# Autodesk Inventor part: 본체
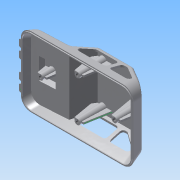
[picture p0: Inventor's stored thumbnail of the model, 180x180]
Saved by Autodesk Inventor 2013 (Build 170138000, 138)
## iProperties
Created: 2015-05
Part Number: 본체
Material: ABS 플라스틱
Document SubType Name: Modeling
Designer: Administrator
Density: 7.85 g/cm^3
Mass: 239.611 g
Surface Area: 315.025 cm^2
Volume: 30.5238 cm^3
Author: Administrator
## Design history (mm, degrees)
sketch "스케치1"
  geometry: L1 (0, 0)-(122, 0); L2 (92, 30)-(53.826, 30); L3 (53.826, 30)-(42, 11.075); L4 (42, 11.075)-(2.412, 9); L5 (2.412, 9)-(0, 0); L6 (122, 0)-(122, 10); L7 (92, 30)-(122, 10); L8 (122, 0)-(118.738, 12.175)
  constraints: 16 end point, 1 horizontal, 1 parallel, 1 perpendicular, 1 point on line
  dimensions: "d0" = 122 distance of L1.start L1.end; "d1" = 105 deg angle of L1 L5; "d2" = 30 distance between parallel lines of L2 L1; "d3" = 30 horizontal distance of L1.end L2.start; "d4" = 9 vertical distance of L1.start L4.end; "d6" = 3 deg angle of L1 L4; "d9" = 125 deg angle of L3 L4; "d10" = 42 horizontal distance of L1.start L3.end; "d33" = 20 vertical distance of L6.end L2.start; "d34" = 105 deg angle of L1 L8
node "작업 평면1"
extrude "돌출4" new body sketch "스케치1" stored distance "d35" = 76; taper "d36" = 0 deg
node "작업 평면4"
sketch "스케치7"
  geometry: L1 (12.175, 38)-(30, 38) reference; L2 (0, 38)-(12.175, 38) reference; L3 (0, -38)-(0, 38) reference; L4 (30, -38)-(30, 38) reference; L5 (30, -38)-(12.175, -38) reference; L6 (12.175, -38)-(0, -38) reference; L7 (0, -38)-(30, -29.962); L8 (0, 38)-(30, 29.962); 1 further point
  constraints: 4 end point, 2 point on line
  dimensions: "d40" = 105 deg angle of L3 L7; "d41" = 105 deg angle of L3 L8
extrude "돌출5" cut sketch "스케치7" stored distance "d42" = 76; taper "d43" = 0 deg
sketch "스케치9"
  geometry: L1 (8.121, 48.588)-(28.121, 48.588); L2 (28.121, 48.588)-(28.121, 22.588); L3 (28.121, 22.588)-(8.121, 22.588); L4 (8.121, 22.588)-(8.121, 48.588); L5 (8.121, 48.588)-(28.121, 22.588); L6 (28.121, 48.588)-(8.121, 22.588); L7 (-2.879, -2.412)-(-2.879, 73.588) reference; 4 further points
  constraints: 12 end point, 4 midpoint, 2 parallel, 1 horizontal, 1 horizontal alignment, 1 perpendicular
  dimensions: "d53" = 11 distance between parallel lines of L4 L7; "d54" = 20 distance between parallel lines of L2 L4; "d55" = 26 distance between parallel lines of L3 L1
extrude "돌출7" join sketch "스케치9" distance "d56" = 5; taper "d57" = -20 deg
fillet "모깎기1" dims "d69" = 12
feature "쉘2" dims "d44" = 2
node "작업 평면5"
sketch "스케치8"
  geometry: L1 (42, 11.075)-(53.826, 30) reference; L2 (53.826, 30)-(92, 30) reference; L3 (112.986, 10)-(90.486, 25); L4 (90.486, 25)-(56.597, 25); L5 (56.597, 25)-(47.224, 10); L6 (47.224, 10)-(112.986, 10); L7 (81.224, 25)-(81.224, 10); L8 (84.986, 25)-(84.986, 10); 3 further points; 1 other entity
  constraints: 12 end point, 4 point on line, 2 perpendicular, 1 parallel, 2 other
  dimensions: "d46" = 5 distance between parallel lines of L4 L2; "d47" = 15 distance between parallel lines of L6 L4; "d48" = 5 dimension on L3; "d49" = 34 distance of L7.end L5.end; "d50" = 28 distance of L3.start L8.end
extrude "돌출6" cut sketch "스케치8" stored distance "d51" = 76; taper "d52" = 0 deg
node "작업 평면6"
sketch "스케치14"
  geometry: L1 (98.679, -73.929)-(0.139, -73.929) reference; L2 (-9.521, -64.27)-(-9.521, -11.73) reference; L3 (0.139, -2.071)-(98.679, -2.071) reference; L4 (108.338, -11.73)-(108.338, -64.27) reference; L5 (98.679, -1.071)-(0.139, -1.071); L6 (-10.521, -11.73)-(-10.521, -64.27); L7 (0.139, -74.929)-(98.679, -74.929); L8 (109.338, -64.27)-(109.338, -11.73); 5 further points; 4 other entities
  constraints: 8 end point, 7 parallel, 16 other
  dimensions: "d87" = 1 distance between parallel lines of L3 L5
extrude "돌출10" join sketch "스케치14" distance "d88" = 1; taper "d89" = 0 deg
node "작업 평면9"
sketch "스케치15" dims "d103" = 4
  geometry: L1 (0, 25)-(0, -25); C1 r 4 at (0, -10); C2 r 4 at (0, 10); 6 further points
  constraints: 2 centre point, 2 end point, 2 vertical alignment, 1 equal radius, 13 other
  dimensions: "d105" = 20 distance of C1.centre C2.centre; "d106" = 10 distance of C1.centre point (0, 0); "d107" = 11 distance of C1.centre point (0, -21); "d108" = 11 distance of C2.centre point (0, 21)
extrude "돌출11" join sketch "스케치15" stored distance "d109" = 1; taper "d110" = 0 deg
sketch "스케치16"
  geometry: L1 (-35, 0)-(-27, 0); L2 (-24, 0)-(-16, 0); L3 (-4, 0)-(4, 0); L4 (7, 0)-(15, 0); A1 r 4 centre (0, 0) between (-4, 0) and (4, 0) reference; A2 r 4 centre (-31, 0) between (-35, 0) and (-27, 0) reference; A3 r 4 centre (-20, 0) between (-24, 0) and (-16, 0) reference; A4 r 4 centre (11, 0) between (7, 0) and (15, 0) reference; 1 further point
  constraints: 8 end point, 8 point on circle, 3 collinear, 2 point on line, 1 horizontal
  dimensions: "d111" = 8 distance of L1.start L1.end; "d112" = 8 distance of L2.start L2.end
extrude "돌출12" cut sketch "스케치16" stored distance "d113" = 1; taper "d114" = 0 deg
sketch "스케치17"
  geometry: 1 further point
node "작업 평면10"
sketch "스케치18"
  geometry: L1 (110.409, 11.591)-(110.409, 64.409) reference; L2 (-11.591, 44)-(-11.591, 32) reference; C1 r 3 at (9.409, 38); C2 r 3 at (89.409, 38); C3 r 3 at (49.409, 60); C4 r 3 at (49.409, 16); 2 further points
  constraints: 4 centre point, 3 equal radius, 2 horizontal alignment, 1 midpoint, 1 vertical alignment
  dimensions: "d116" = 6 diameter of C1; "d118" = 21 distance from line of C2.centre L1; "d119" = 40 horizontal distance of C4.centre C2.centre; "d120" = 40 horizontal distance of C4.centre C1.centre; "d121" = 44 distance of C4.centre C3.centre; "d122" = 22 vertical distance of C2.centre C4.centre
extrude "돌출13" join sketch "스케치18" stored distance "d123" = 1; taper "d124" = 2 deg
node "작업 평면11"
node "작업 평면12"
sketch "스케치21"
  geometry: L1 (-5, 1)-(5, 1); L2 (5, 1)-(5, -1); L3 (5, -1)-(-5, -1); L4 (-5, -1)-(-5, 1); L5 (-5, 1)-(5, -1); L6 (5, 1)-(-5, -1); L7 (-5, -43)-(5, -43); L8 (5, -43)-(5, -45); L9 (5, -45)-(-5, -45); L10 (-5, -45)-(-5, -43); L11 (-5, -43)-(5, -45); L12 (5, -43)-(-5, -45); L13 (35, -21)-(45, -21); L14 (45, -21)-(45, -23); L15 (45, -23)-(35, -23); L16 (35, -23)-(35, -21); L17 (35, -21)-(45, -23); L18 (45, -21)-(35, -23); L19 (-45, -21)-(-35, -21); L20 (-35, -21)-(-35, -23); L21 (-35, -23)-(-45, -23); L22 (-45, -23)-(-45, -21); L23 (-45, -21)-(-35, -23); L24 (-35, -21)-(-45, -23); C1 r 3 at (0, 0) reference; C2 r 3 at (-40, -22) reference; C3 r 3 at (40, -22) reference; C4 r 3 at (0, -44) reference; 1 further point
  constraints: 48 end point, 8 midpoint, 8 parallel, 4 horizontal, 4 perpendicular
  dimensions: "d137" = 2 distance of L1.end L2.end; "d139" = 10 distance of L2.end L3.end; "d140" = 2 distance of L19.end L20.end; "d141" = 10 horizontal distance of L19.start L20.end; "d142" = 2 distance of L7.end L8.end; "d143" = 10 distance of L8.end L9.end; "d144" = 2 distance of L13.end L14.end; "d145" = 10 distance of L14.end L15.end
extrude "돌출15" join sketch "스케치21" stored distance "d146" = 2; taper "d147" = 0 deg
node "작업 평면13"
sketch "스케치23"
  geometry: L1 (16, 2)-(18.098, 2) reference; L2 (23.902, 2)-(26, 2) reference; L3 (96, 2)-(98.098, 2) reference; L4 (103.902, 2)-(106, 2) reference; L5 (16, 2)-(13.916, 13.82); L6 (26, 2)-(28.084, 13.82); L7 (13.916, 13.82)-(28.084, 13.82); L8 (96, 2)-(91.265, 28.856); L9 (91.265, 28.856)-(110.735, 28.856); L10 (110.735, 28.856)-(106, 2); L11 (16, 2)-(26, 2); L12 (96, 2)-(106, 2); 1 further point
  constraints: 16 end point, 3 parallel, 2 equal length, 1 collinear
  dimensions: "d149" = 20 deg angle of L6 L5; "d150" = 14.16846 distance of L5.end L6.end; "d152" = 20 deg angle of L8 L10; "d154" = 19.47074 distance of L8.end L9.end
extrude "돌출16" join sketch "스케치23" stored distance "d155" = 2; taper "d156" = 0 deg
sketch "스케치24"
  geometry: L1 (110.735, 28.856)-(93.717, 28.856) reference; L2 (108.945, 18.703)-(110.735, 28.856) reference; L3 (92, 30)-(104.626, 21.583) reference; L4 (104.626, 21.583)-(118.738, 12.175) reference; L5 (93.717, 28.856)-(110.735, 28.856); L6 (108.945, 18.703)-(110.735, 28.856); L7 (108.945, 18.703)-(93.717, 28.856); 1 further point
  constraints: 6 end point, 3 collinear
extrude "돌출17" cut sketch "스케치24" stored distance "d157" = 2; taper "d158" = 0 deg
fillet "모깎기2" dims "d166" = 3
fillet "모깎기3" dims "d167" = 3
fillet "모깎기4" dims "d168" = 3
chamfer "모따기1" distance "d169" = 1; stored, may be unused: second distance "d170" = 2, angle "d171" = 45 deg
node "작업 평면14"
sketch "스케치26"
  geometry: L1 (-7.902, 0)-(-5.805, 0) reference; L2 (-7.902, 0)-(-7.902, 26) reference; L3 (2.098, 0)-(2.098, 26) reference; L4 (0, 0)-(2.098, 0) reference; L5 (2.098, 0)-(6.875, 27.093); L6 (6.875, 27.093)-(-12.68, 27.093); L7 (-12.68, 27.093)-(-7.902, 0); L8 (-7.902, 0)-(2.098, 0); 1 further point
  constraints: 8 end point, 1 collinear, 1 equal length, 1 parallel
  dimensions: "d172" = 20 deg angle of L5 L7; "d173" = 19.55442 distance of L5.end L6.end
extrude "돌출18" join sketch "스케치26" stored distance "d176" = 2; taper "d177" = 0 deg
sketch "스케치27"
  geometry: L1 (-10.958, 26.59)-(-12.231, 24.551) reference; L2 (-10.563, 27.093)-(-12.68, 27.093) reference; L3 (-12.68, 27.093)-(-12.231, 24.551) reference; L4 (-10.958, 26.59)-(-12.231, 24.551) reference; L5 (-10.563, 27.093)-(-12.68, 27.093) reference; L6 (-12.68, 27.093)-(-12.231, 24.551) reference; A1 r 3 centre (-8.414, 25) between (-10.563, 27.093) and (-10.958, 26.59) reference; A2 r 3 centre (-8.414, 25) between (-10.563, 27.093) and (-10.958, 26.59) reference; 1 further point
extrude "돌출19" cut sketch "스케치27" stored distance "d178" = 2; taper "d179" = 0 deg
node "작업 평면15"
sketch "스케치28"
  geometry: L1 (-12.487, 26)-(-7.902, 0) reference; 1 further point
sketch "스케치29"
  geometry: L1 (-55.489, -33.66)-(-55.489, -21.66) reference; L2 (66.511, -1.251)-(66.511, -54.068) reference; 3 further points
  constraints: 1 horizontal alignment, 1 midpoint, 1 other
  dimensions: "d180" = 50 distance from line of L2 point (16.511, -27.66)
feature "엠보싱1" sketch "스케치29" dims "d0" = 122, "d1" = 105 deg, "d2" = 30, "d3" = 30, "d4" = 9, "d6" = 3 deg, "d9" = 125 deg, "d10" = 42, "d33" = 20, "d34" = 105 deg, "d181" = 0.58, "d182" = 0
sketch "스케치25"
  geometry: C1 r 3 at (0, 0) reference; C2 r 3 at (-40, -22) reference; C3 r 3 at (0, -44) reference; C4 r 3 at (40, -22) reference; 5 further points
  constraints: 4 coincident
hole "구멍1" sketch "스케치25" at (0, -44), (0, 0), (40, -22), (-40, -22) diameter "d159" = 3.242; stored, may be unused: countersink angle "d163" = 90 deg, drill point angle "d165" = 118 deg; dims "d160" = 9, "d161" = 4, "d162" = 2, "d164" = 11
node "솔리드2"
mirror "대칭1"
node "투영된 루프3"
node "투영된 루프4"
node "투영된 루프5"
other parameters: "d15" = 0, "d37" = 0, "d45" = 0, "d70" = -1, "d90" = -2, "d115" = 0, "d125" = 0, "d136" = -2, "d148" = 0
